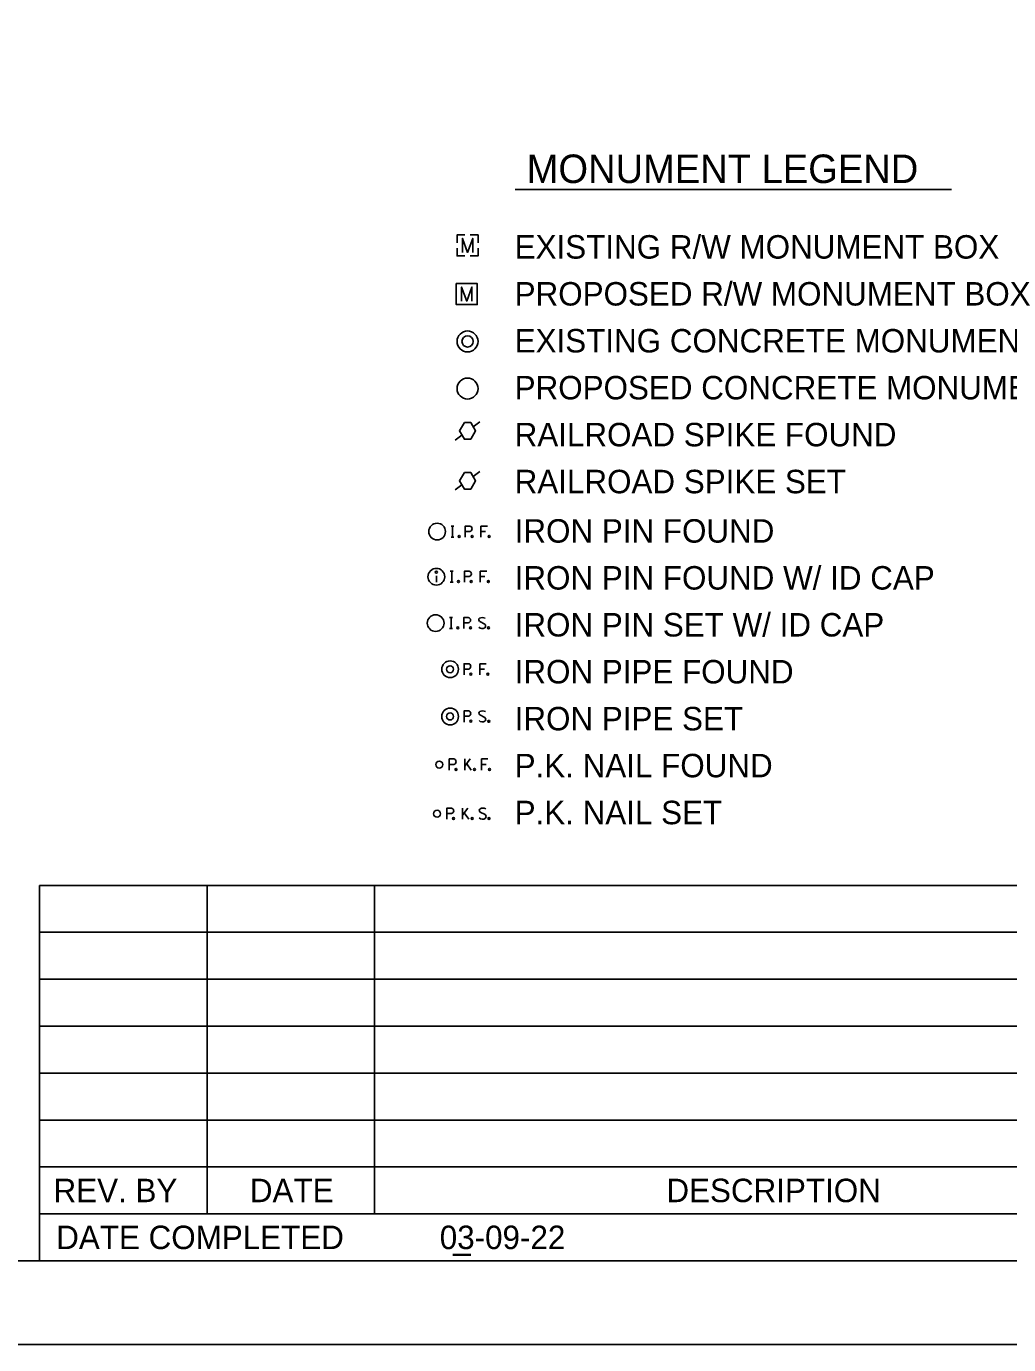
# Model space of a CAD drawing. Extents: x 54.5 to 92.3, y 4.7 to 26.7.
# Drawn here: x 79.64 to 85.5, y 4.72 to 12.58 of the extents above; entities that cross this region are included whole.
import ezdxf

# ---------------------------------------------------------------- set-up
doc = ezdxf.new("R2010")
doc.units = 0
for name, color, linetype in [('SH_Border', 7, 'Continuous'), ('SH_Cut_Line', 7, 'Continuous'), ('SH_Text', 7, 'Continuous')]:
    doc.layers.add(name, color=color, linetype=linetype)

msp = doc.modelspace()

# ---------------------------------------------------------------- linework, layer by layer
at = {"layer": 'SH_Border'}
msp.add_lwpolyline([(56.0231, 26.2167), (88.0231, 26.2167), (88.0231, 5.2167), (56.0231, 5.2167)], close=True, dxfattribs=at)
at = {"layer": 'SH_Cut_Line'}
msp.add_lwpolyline([(54.5231, 4.7167), (88.5231, 4.7167), (88.5231, 26.7167), (54.5231, 26.7167)], close=True, dxfattribs=at)
at = {"layer": 'SH_Text'}
for p, q in [((82.5578, 11.6091), (85.1616, 11.6091)), ((82.2741, 11.2748), (82.2741, 11.2748)), ((82.2694, 10.9843), (82.2694, 10.9843)), ((82.3478, 10.2229), (82.3077, 10.1929)), ((82.2406, 10.1429), (82.2005, 10.113)), ((82.3478, 9.9259), (82.3077, 9.8959)), ((82.2406, 9.8459), (82.2005, 9.816)), ((82.1757, 9.6007), (82.1923, 9.6007)), ((82.1757, 9.6007), (82.1923, 9.6007)), ((82.184, 9.534), (82.184, 9.6007)), ((82.3542, 9.534), (82.3542, 9.6007)), ((82.3542, 9.6007), (82.3927, 9.6007)), ((82.1757, 9.534), (82.1923, 9.534)), ((82.2607, 9.5688), (82.2873, 9.5688)), ((82.3542, 9.5683), (82.3817, 9.5683)), ((82.088, 9.303), (82.088, 9.2662)), ((82.1713, 9.3315), (82.188, 9.3315)), ((82.1713, 9.3315), (82.188, 9.3315)), ((82.1797, 9.2648), (82.1797, 9.3315)), ((82.2563, 9.2995), (82.283, 9.2995)), ((82.35, 9.2648), (82.35, 9.3315)), ((82.35, 9.3315), (82.3883, 9.3315)), ((82.35, 9.299), (82.3773, 9.299)), ((82.1713, 9.2648), (82.188, 9.2648)), ((82.167, 9.055), (82.1837, 9.055)), ((82.167, 9.055), (82.1837, 9.055)), ((82.1754, 8.9883), (82.1754, 9.055)), ((82.167, 8.9883), (82.1837, 8.9883)), ((82.252, 9.0231), (82.2787, 9.0231)), ((82.3464, 9.0312), (82.3769, 9.0154)), ((82.2533, 8.7474), (82.2799, 8.7474)), ((82.3469, 8.7126), (82.3469, 8.7793)), ((82.3469, 8.7793), (82.3853, 8.7793)), ((82.3469, 8.7469), (82.3743, 8.7469)), ((82.2533, 8.4659), (82.2799, 8.4659)), ((82.3476, 8.4741), (82.3782, 8.4583)), ((82.2586, 8.144), (82.2586, 8.2107)), ((82.2586, 8.1682), (82.2906, 8.2107)), ((82.269, 8.1819), (82.2965, 8.144)), ((82.357, 8.144), (82.357, 8.2107)), ((82.357, 8.2107), (82.3954, 8.2107)), ((82.1651, 8.1788), (82.1918, 8.1788)), ((82.357, 8.1783), (82.3843, 8.1783)), ((82.1509, 7.8858), (82.1776, 7.8858)), ((82.2436, 7.8511), (82.2436, 7.9177)), ((82.2436, 7.8752), (82.2756, 7.9177)), ((82.2539, 7.889), (82.2814, 7.8511)), ((82.3493, 7.8944), (82.3799, 7.8786)), ((79.7197, 7.4567), (79.7197, 5.2167)), ((79.7197, 7.4567), (86.5231, 7.4567)), ((80.7197, 7.4567), (80.7197, 5.4967)), ((81.7197, 7.4567), (81.7197, 5.4967)), ((79.7197, 7.1767), (86.5231, 7.1767)), ((79.7197, 6.8967), (86.5231, 6.8967)), ((79.7197, 6.6167), (86.5231, 6.6167)), ((79.7197, 6.3367), (86.5231, 6.3367)), ((79.7197, 6.0567), (86.5231, 6.0567)), ((79.7197, 5.7767), (86.5231, 5.7767)), ((79.7197, 5.4967), (86.5231, 5.4967))]:
    msp.add_line(p, q, dxfattribs=at)
for points in [[(82.2116, 11.2906), (82.2116, 11.3374), (82.2584, 11.3374)], [(82.2889, 11.3374), (82.3367, 11.3374), (82.3367, 11.2906)], [(82.2584, 11.2123), (82.2116, 11.2123), (82.2116, 11.259)], [(82.2433, 11.2331), (82.2433, 11.3165), (82.2741, 11.2331), (82.3049, 11.3165), (82.3049, 11.2331)], [(82.3367, 11.259), (82.3367, 11.2123), (82.2889, 11.2123)], [(82.2069, 11.0469), (82.332, 11.0469), (82.332, 10.9218), (82.2069, 10.9218), (82.2069, 11.0469)], [(82.2386, 10.9427), (82.2386, 11.026), (82.2694, 10.9427), (82.3003, 11.026), (82.3003, 10.9427)], [(82.2873, 9.6007), (82.2607, 9.6007), (82.2607, 9.534)], [(82.283, 9.3315), (82.2563, 9.3315), (82.2563, 9.2648)], [(82.2787, 9.055), (82.252, 9.055), (82.252, 8.9883)], [(82.2799, 8.7793), (82.2533, 8.7793), (82.2533, 8.7126)], [(82.2799, 8.4978), (82.2533, 8.4978), (82.2533, 8.4312)], [(82.1918, 8.2107), (82.1651, 8.2107), (82.1651, 8.144)], [(82.1776, 7.9177), (82.1509, 7.9177), (82.1509, 7.8511)]]:
    msp.add_lwpolyline(points, dxfattribs=at)
for points in [[(82.2553, 10.2179), (82.2928, 10.2179), (82.3224, 10.1679), (82.2928, 10.1179), (82.2553, 10.1179), (82.2258, 10.1679)], [(82.2553, 9.9209), (82.2928, 9.9209), (82.3224, 9.8709), (82.2928, 9.8209), (82.2553, 9.8209), (82.2258, 9.8709)]]:
    msp.add_lwpolyline(points, close=True, dxfattribs=at)
for centre, radius in [((82.2741, 10.702), 0.0625), ((82.2741, 10.702), 0.0333), ((82.2741, 10.4206), 0.0625), ((82.0923, 9.5674), 0.05), ((82.2241, 9.5385), 0.00583), ((82.3008, 9.5385), 0.00583), ((82.4025, 9.5385), 0.00583), ((82.088, 9.2982), 0.05), ((82.088, 9.3253), 0.00667), ((82.2198, 9.2693), 0.00583), ((82.2965, 9.2693), 0.00583), ((82.3982, 9.2693), 0.00583), ((82.0837, 9.0217), 0.05), ((82.2155, 8.9929), 0.00583), ((82.2922, 8.9929), 0.00583), ((82.3991, 8.9925), 0.00583), ((82.1699, 8.746), 0.05), ((82.1699, 8.746), 0.0206), ((82.2934, 8.7172), 0.00583), ((82.3951, 8.7172), 0.00583), ((82.1699, 8.4645), 0.05), ((82.1699, 8.4645), 0.0208), ((82.2934, 8.4357), 0.00583), ((82.4003, 8.4353), 0.00583), ((82.1052, 8.1773), 0.0207), ((82.2052, 8.1486), 0.00583), ((82.3149, 8.1486), 0.00583), ((82.4052, 8.1486), 0.00583), ((82.0923, 7.8844), 0.0206), ((82.191, 7.8556), 0.00583), ((82.302, 7.8556), 0.00583), ((82.402, 7.8556), 0.00583)]:
    msp.add_circle(centre, radius, dxfattribs=at)
for centre, radius, start, end in [((82.2848, 9.5847), 0.0162, 278.88026, 81.11974), ((82.2806, 9.3155), 0.0162, 278.88026, 81.11974), ((82.2762, 9.0391), 0.0162, 278.88026, 81.11974), ((82.3529, 9.0411), 0.0118, 126.25873, 236.36755), ((82.3626, 9.02), 0.0349, 61.34633, 118.65367), ((82.3612, 9.0161), 0.0276, 223.66947, 304.39628), ((82.367, 9.0044), 0.0148, 311.48833, 47.93584), ((82.2775, 8.7634), 0.0162, 278.88026, 81.11974), ((82.2775, 8.4819), 0.0162, 278.88026, 81.11974), ((82.3639, 8.4628), 0.0349, 61.34633, 118.65367), ((82.3541, 8.484), 0.0118, 126.25873, 236.36755), ((82.3624, 8.459), 0.0276, 223.66947, 304.39628), ((82.3682, 8.4473), 0.0148, 311.48833, 47.93584), ((82.1893, 8.1947), 0.0162, 278.88026, 81.11974), ((82.1751, 7.9018), 0.0162, 278.88026, 81.11974), ((82.3559, 7.9043), 0.0118, 126.25873, 236.36755), ((82.3656, 7.8832), 0.0349, 61.34633, 118.65367), ((82.37, 7.8676), 0.0148, 311.48833, 47.93584), ((82.3642, 7.8793), 0.0276, 223.66947, 304.39628)]:
    msp.add_arc(centre, radius, start, end, dxfattribs=at)

# ---------------------------------------------------------------- texts
for s, height, p in [('MONUMENT LEGEND', 0.17, (82.6269, 11.647)), ('EXISTING R/W MONUMENT BOX', 0.14, (82.5552, 11.1961)), ('PROPOSED R/W MONUMENT BOX', 0.14, (82.5552, 10.9161)), ('EXISTING CONCRETE MONUMENT', 0.14, (82.5552, 10.6361)), ('PROPOSED CONCRETE MONUMENT', 0.14, (82.5552, 10.3561)), ('RAILROAD SPIKE FOUND', 0.14, (82.5552, 10.0761)), ('RAILROAD SPIKE SET', 0.14, (82.5552, 9.7961)), ('IRON PIN FOUND', 0.14, (82.5552, 9.5015)), ('IRON PIN FOUND W/ ID CAP', 0.14, (82.5552, 9.2215)), ('IRON PIN SET W/ ID CAP', 0.14, (82.5552, 8.9415)), ('IRON PIPE FOUND', 0.14, (82.5552, 8.6615)), ('IRON PIPE SET', 0.14, (82.5552, 8.3815)), ('P.K. NAIL FOUND', 0.14, (82.5552, 8.1015)), ('P.K. NAIL SET', 0.14, (82.5552, 7.8215)), ('REV. BY', 0.14, (79.8039, 5.5667)), ('DATE', 0.14, (80.9753, 5.5667)), ('DESCRIPTION', 0.14, (83.4607, 5.5667)), ('DATE COMPLETED           03-09-22', 0.14, (79.8197, 5.2867)), ('          _', 0.14, (81.6675, 5.2867))]:
    msp.add_text(s, height=height, dxfattribs=at).set_placement(p)

doc.saveas('drawing.dxf')
